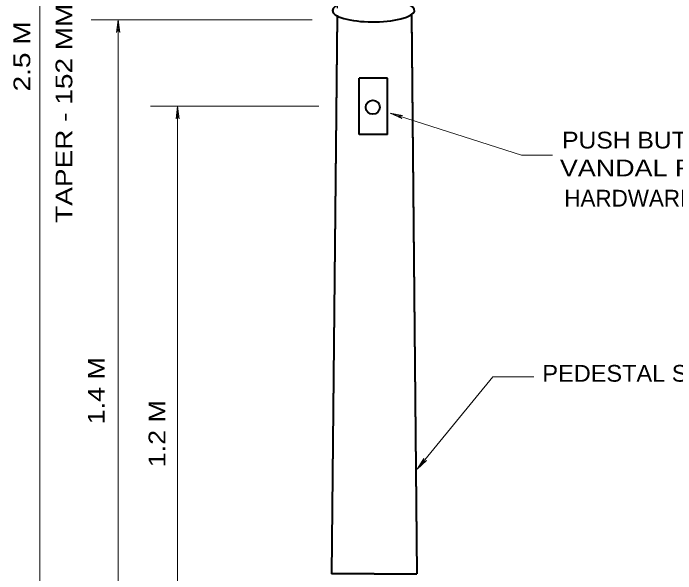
# Model space of a CAD drawing. Extents: x 312583 to 312854, y 144419 to 144597.
# Drawn here: x 312799.39 to 312829.45, y 144516.42 to 144541.86 of the extents above; entities that cross this region are included whole.
import ezdxf

# ---------------------------------------------------------------- set-up
doc = ezdxf.new("R2010")
doc.units = 0
doc.header["$LTSCALE"] = 0.3
doc.linetypes.add('SHORT_DASHED', pattern=[2.7, 1.5, -1.2])
doc.layers.add('1', color=7, linetype='Continuous', lineweight=40)
doc.layers.add('2', color=7, linetype='Continuous', lineweight=13)

msp = doc.modelspace()

# ---------------------------------------------------------------- linework, layer by layer
at = {"layer": '1', "linetype": 'SHORT_DASHED', "lineweight": 25}
for p, q in [((312814.2042, 144553.8766), (312814.0815, 144541.7786)), ((312817.2325, 144553.9993), (312817.4548, 144541.7939))]:
    msp.add_line(p, q, dxfattribs=at)
at = {"layer": '1'}
for p, q in [((312817.4548, 144541.8093), (312817.7078, 144516.4173)), ((312814.0815, 144541.7786), (312813.8285, 144516.4173)), ((312814.0815, 144541.7709), (312813.8285, 144516.4173)), ((312814.0815, 144541.7479), (312813.8285, 144516.4173)), ((312814.0815, 144541.7479), (312813.8285, 144516.4173)), ((312817.4548, 144541.7939), (312817.7078, 144516.4173)), ((312817.4548, 144541.7709), (312817.7078, 144516.4173)), ((312817.4548, 144541.7479), (312817.7078, 144516.4173)), ((312816.3662, 144538.9113), (312815.0858, 144538.9113)), ((312815.0858, 144536.3583), (312815.0858, 144538.9113)), ((312816.3662, 144536.3583), (312816.3662, 144538.9113)), ((312816.3662, 144536.3583), (312815.0858, 144536.3583)), ((312815.7682, 144516.4173), (312813.8285, 144516.4173)), ((312815.7682, 144516.4173), (312813.8285, 144516.4173)), ((312815.7682, 144516.4173), (312813.8285, 144516.4173)), ((312815.7682, 144516.4173), (312813.8285, 144516.4173)), ((312815.7682, 144516.4173), (312813.8285, 144516.4173)), ((312815.7682, 144516.4173), (312813.8285, 144516.4173)), ((312815.7682, 144516.4173), (312813.8285, 144516.4173)), ((312815.7682, 144516.4173), (312813.8285, 144516.4173)), ((312815.7682, 144516.4173), (312817.7078, 144516.4173)), ((312815.7682, 144516.4173), (312817.7078, 144516.4173)), ((312815.7682, 144516.4173), (312817.7078, 144516.4173)), ((312815.7682, 144516.4173), (312817.7078, 144516.4173)), ((312815.7682, 144516.4173), (312817.7078, 144516.4173)), ((312815.7682, 144516.4173), (312817.7078, 144516.4173)), ((312815.7682, 144516.4173), (312817.7078, 144516.4173)), ((312815.7682, 144516.4173), (312817.7078, 144516.4173))]:
    msp.add_line(p, q, dxfattribs=at)
msp.add_circle((312815.7017, 144537.59), 0.3194, dxfattribs=at)
msp.add_ellipse((312815.7372, 144541.984), major_axis=(1.8601, 0.0073), ratio=0.278719, start_param=2.3620161, end_param=6.9800621, dxfattribs=at)
at = {"layer": '2'}
for p, q in [((312800.5894, 144570.0456), (312800.5894, 144506.8186)), ((312812.9545, 144541.5639), (312802.9216, 144541.5639)), ((312804.153, 144541.5639), (312804.0763, 144540.9889)), ((312804.153, 144541.5639), (312804.153, 144506.8646)), ((312804.153, 144541.5639), (312804.222, 144540.9889)), ((312804.0763, 144540.9889), (312804.153, 144541.1729)), ((312804.222, 144540.9889), (312804.153, 144541.1729)), ((312813.2535, 144537.6463), (312805.6148, 144537.6463)), ((312806.8427, 144537.6463), (312806.7737, 144537.0636)), ((312806.8427, 144537.6463), (312806.7737, 144537.0636)), ((312806.8427, 144537.6463), (312806.8427, 144506.9106)), ((312806.8427, 144537.6463), (312806.9194, 144537.0636)), ((312806.8427, 144537.6463), (312806.9194, 144537.0636)), ((312816.4888, 144537.3243), (312822.4535, 144535.4229)), ((312816.4888, 144537.3243), (312817.0178, 144537.0789)), ((312816.4888, 144537.3243), (312817.0562, 144537.2169)), ((312806.7737, 144537.0636), (312806.8427, 144537.2476)), ((312806.7737, 144537.0636), (312806.8427, 144537.2476)), ((312806.9194, 144537.0636), (312806.8427, 144537.2476)), ((312806.9194, 144537.0636), (312806.8427, 144537.2476)), ((312817.0562, 144537.2169), (312816.8645, 144537.2093)), ((312817.0178, 144537.0789), (312816.8645, 144537.2093)), ((312823.8605, 144535.4229), (312822.4535, 144535.4229)), ((312817.7155, 144521.1629), (312821.1578, 144525.3566)), ((312823.0097, 144525.3566), (312821.1578, 144525.3566)), ((312817.7155, 144521.1629), (312818.0222, 144521.6536)), ((312817.7155, 144521.1629), (312818.1372, 144521.5616)), ((312818.0222, 144521.6536), (312817.9608, 144521.4619)), ((312818.1372, 144521.5616), (312817.9608, 144521.4619))]:
    msp.add_line(p, q, dxfattribs=at)

# ---------------------------------------------------------------- texts
for s, width, p in [('TAPER - 152 MM O.D. TO 111 MM O.D', 1.25, (312802.0686, 144532.3434)), ('2.5 M  MINIMUM', 1.25, (312800.1596, 144538.3103)), ('1.4 M', 1.2, (312803.5337, 144523.1974)), ('1.2 M', 1.2, (312806.2905, 144521.2501))]:
    msp.add_text(s, height=0.76, rotation=90, dxfattribs=dict(at, width=width)).set_placement(p)
for s, width, p in [('PUSH BUTTON ASSEMBLY WITH', 1.1, (312824.2955, 144535.7209)), ('VANDAL RESISTANT STN. STL.', 1.2, (312824.1958, 144534.4559)), ('PEDESTAL STANDARD', 1.05, (312823.399, 144525.1333))]:
    msp.add_text(s, height=0.76, dxfattribs=dict(at, width=width)).set_placement(p)
msp.add_text('HARDWARE.', height=0.76, dxfattribs=at).set_placement((312824.3951, 144533.0836))

doc.saveas('drawing.dxf')
